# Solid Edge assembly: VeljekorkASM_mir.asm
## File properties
Author: KULL
Template: Iso Metric Assembly.asm
Last saved by: KULL
Revision: 2
Application: Solid Edge
Username: KULL
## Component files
rehvikork_mir.par
rehvikork_logo_mir.par
VeljekorkASM.asm
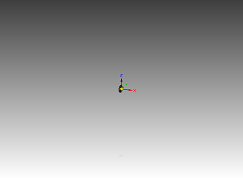
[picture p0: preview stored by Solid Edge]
